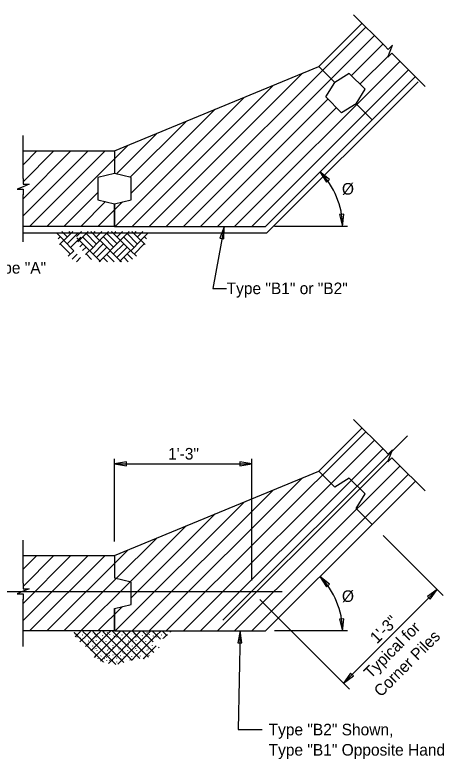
# Model space of a CAD drawing. Extents: x 0.4 to 30.4, y 0.1 to 19.4.
# Drawn here: x 11.03 to 16.63, y 0.42 to 10.14 of the extents above; entities that cross this region are included whole.
import ezdxf

# ---------------------------------------------------------------- set-up
doc = ezdxf.new("R2010")
doc.units = 0
for name, color, linetype in [('Dimension', 7, 'Continuous'), ('Miscellaneous', 7, 'Continuous'), ('SheetPileConc', 7, 'Continuous'), ('TextStructures', 7, 'Continuous')]:
    doc.layers.add(name, color=color, linetype=linetype)

msp = doc.modelspace()

# ---------------------------------------------------------------- linework, layer by layer
at = {"layer": 'Dimension'}
for p, q in [((15.4473, 10.1428), (15.8492, 9.7409)), ((15.9982, 9.5919), (16.3805, 9.2096)), ((14.3167, 7.295), (16.2894, 9.2679)), ((11.1364, 8.0057), (11.1364, 8.5658)), ((11.1364, 7.1795), (11.1364, 7.7951)), ((11.1364, 7.295), (14.3167, 7.295)), ((15.3652, 7.3812), (14.416, 7.3812)), ((15.4473, 4.8586), (15.8492, 4.4567)), ((12.3278, 3.2671), (12.3278, 4.3456)), ((12.3278, 4.2799), (14.1178, 4.2799)), ((14.1178, 2.7541), (14.1178, 4.3456)), ((15.9982, 4.3077), (16.3805, 3.9254)), ((15.8338, 3.3439), (16.6166, 2.5612)), ((11.1364, 2.7215), (11.1364, 3.2816)), ((15.315, 1.4172), (16.5378, 2.64)), ((11.1364, 1.8953), (11.1364, 2.5109)), ((14.2235, 2.5087), (15.3938, 1.3384)), ((15.3652, 2.097), (14.416, 2.097))]:
    msp.add_line(p, q, dxfattribs=at)
for points in [[(15.998, 9.5921), (15.9467, 9.6434), (15.8919, 9.5886), (15.9229, 9.6672), (15.9538, 9.7459), (15.899, 9.6911), (15.8478, 9.7423)], [(11.1364, 8.0055), (11.1364, 7.933), (11.2139, 7.933), (11.1364, 7.8993), (11.0589, 7.8655), (11.1364, 7.8655), (11.1364, 7.793)], [(13.7593, 7.3769), (13.6131, 6.5692), (13.7903, 6.5692)], [(15.998, 4.3079), (15.9467, 4.3592), (15.8919, 4.3044), (15.9229, 4.383), (15.9538, 4.4617), (15.899, 4.4069), (15.8478, 4.4581)], [(11.1364, 2.7213), (11.1364, 2.6488), (11.2139, 2.6488), (11.1364, 2.615), (11.0589, 2.5813), (11.1364, 2.5813), (11.1364, 2.5088)], [(13.9657, 2.097), (13.9426, 0.8111), (14.2532, 0.8111)]]:
    msp.add_lwpolyline(points, dxfattribs=at)
for points in [[(15.0078, 8.0922), (15.0925, 7.9584), (15.1318, 7.9937)], [(15.3028, 7.3805), (15.3176, 7.5382), (15.2648, 7.5342)], [(13.7593, 7.3769), (13.7027, 7.2289), (13.7546, 7.2186)], [(12.3278, 4.2798), (12.484, 4.2534), (12.484, 4.3063)], [(14.1178, 4.2798), (13.9616, 4.3063), (13.9616, 4.2534)], [(15.0078, 2.808), (15.0925, 2.6741), (15.1318, 2.7095)], [(16.5378, 2.64), (16.4086, 2.5483), (16.446, 2.5108)], [(15.3028, 2.0962), (15.3176, 2.254), (15.2648, 2.25)], [(13.9657, 2.097), (13.9356, 1.9415), (13.9885, 1.9403)], [(15.315, 1.4172), (15.4442, 1.509), (15.4067, 1.5464)]]:
    msp.add_lwpolyline(points, close=True, dxfattribs=at)
for centre in [(14.2966, 7.3812), (14.2966, 2.097)]:
    msp.add_arc(centre, 1.0053, 0, 45.00083, dxfattribs=at)
at = {"layer": 'Miscellaneous'}
for p, q in [((13.004, 7.3812), (15.6065, 9.9836)), ((13.2268, 7.3812), (15.7178, 9.8723)), ((15.4182, 9.35), (15.8292, 9.7609)), ((13.8949, 7.3812), (16.0519, 9.5382)), ((15.5296, 9.2386), (15.9007, 9.6097)), ((12.7813, 7.3812), (14.7824, 9.3823)), ((14.1177, 7.3812), (16.1633, 9.4268)), ((12.5586, 7.3812), (14.4021, 9.2248)), ((12.3358, 7.3812), (14.0219, 9.0673)), ((13.4495, 7.3812), (15.112, 9.0437)), ((12.5444, 7.8125), (13.6417, 8.9098)), ((13.6723, 7.3812), (15.2233, 8.9324)), ((12.5313, 8.0222), (13.2615, 8.7524)), ((12.3512, 8.0648), (12.8813, 8.5949)), ((11.1364, 7.7409), (11.7611, 8.3657)), ((11.1364, 7.5182), (11.9838, 8.3657)), ((11.1364, 8.1864), (11.3156, 8.3657)), ((11.1364, 7.9637), (11.5383, 8.3657)), ((11.2221, 7.3812), (12.2065, 8.3657)), ((11.4449, 7.3812), (12.501, 8.4374)), ((11.6676, 7.3812), (12.1113, 7.8249)), ((11.8904, 7.3812), (12.2128, 7.7037)), ((12.1131, 7.3812), (12.4333, 7.7016)), ((11.5768, 7.2907), (11.6664, 7.2011)), ((11.6426, 7.3132), (11.7105, 7.2453)), ((11.7841, 7.3132), (11.6692, 7.1983)), ((11.7311, 7.3132), (11.7548, 7.2895)), ((11.8324, 7.2482), (11.8974, 7.3132)), ((11.9859, 7.3132), (11.8519, 7.1792)), ((12.0204, 7.3132), (12.1353, 7.1983)), ((12.0733, 7.3132), (12.0496, 7.2895)), ((12.1619, 7.3132), (12.0939, 7.2453)), ((12.2501, 7.3132), (12.138, 7.2011)), ((12.5211, 7.3132), (12.2735, 7.0657)), ((12.2904, 7.3132), (12.5379, 7.0658)), ((12.3174, 7.2863), (12.3442, 7.3132)), ((12.3615, 7.2422), (12.4325, 7.3132)), ((12.5555, 7.3132), (12.6704, 7.1983)), ((12.6085, 7.3132), (12.5848, 7.2895)), ((12.697, 7.3132), (12.629, 7.2453)), ((12.7627, 7.2907), (12.6732, 7.2011)), ((11.6193, 7.2426), (11.5939, 7.2172)), ((11.6636, 7.1983), (11.61, 7.1447)), ((11.7989, 7.063), (11.6664, 7.1955)), ((11.8456, 7.2861), (11.7135, 7.1541)), ((11.8897, 7.242), (11.7576, 7.1099)), ((11.8371, 7.2313), (12.0027, 7.0658)), ((11.9148, 7.242), (12.0468, 7.1099)), ((11.9589, 7.2861), (12.091, 7.1541)), ((12.0055, 7.063), (12.138, 7.1955)), ((12.1408, 7.1983), (12.2735, 7.0657)), ((12.1851, 7.2426), (12.3178, 7.1099)), ((12.2292, 7.2867), (12.3619, 7.1541)), ((12.4499, 7.242), (12.582, 7.1099)), ((12.494, 7.2861), (12.6261, 7.1541)), ((12.5406, 7.063), (12.6732, 7.1955)), ((12.676, 7.1983), (12.7296, 7.1447)), ((12.7202, 7.2426), (12.7456, 7.2172)), ((11.7546, 7.0187), (11.6221, 7.1512)), ((11.9143, 7.1542), (11.8755, 7.1153)), ((11.9586, 7.1099), (11.9136, 7.0649)), ((12.0498, 7.0187), (12.1823, 7.1512)), ((12.0939, 6.9746), (12.2264, 7.1071)), ((12.4494, 7.1542), (12.3172, 7.0219)), ((12.4937, 7.1099), (12.3615, 6.9776)), ((12.5849, 7.0187), (12.7174, 7.1512)), ((11.7989, 7.063), (11.7255, 6.9896)), ((11.8428, 7.0192), (11.7775, 6.9538)), ((12.0027, 7.0658), (11.9517, 7.0147)), ((11.9617, 7.0192), (12.0308, 6.95)), ((12.0055, 7.063), (12.1473, 6.9213)), ((12.2707, 7.0629), (12.1273, 6.9195)), ((12.2264, 7.0186), (12.3256, 6.9195)), ((12.2707, 7.0629), (12.4028, 6.9307)), ((12.5379, 7.0658), (12.4056, 6.9335)), ((12.4968, 7.0192), (12.5621, 6.9538)), ((12.5406, 7.063), (12.614, 6.9896)), ((11.8869, 6.975), (11.8313, 6.9195)), ((12.1823, 6.9745), (12.2373, 6.9195)), ((12.3971, 6.9195), (12.4056, 6.928)), ((12.4084, 6.9307), (12.4197, 6.9195)), ((12.4527, 6.975), (12.5082, 6.9195)), ((13.004, 2.097), (15.6065, 4.6994)), ((13.2268, 2.097), (15.7178, 4.5881)), ((16.1502, 4.6468), (13.7399, 2.2366)), ((15.4182, 4.0658), (15.8292, 4.4767)), ((15.5296, 3.9544), (15.9007, 4.3255)), ((13.4495, 2.097), (15.5346, 4.1822)), ((13.8949, 2.097), (16.0519, 4.254)), ((12.7813, 2.097), (14.7824, 4.0981)), ((14.1177, 2.097), (16.1633, 4.1426)), ((12.5586, 2.097), (14.4021, 3.9406)), ((13.6723, 2.097), (15.5296, 3.9544)), ((12.3358, 2.097), (14.0219, 3.7831)), ((12.5444, 2.5283), (13.6417, 3.6256)), ((12.5313, 2.738), (13.2615, 3.4682)), ((12.3512, 2.7806), (12.8813, 3.3107)), ((11.4449, 2.097), (12.501, 3.1532)), ((11.1364, 2.4567), (11.7611, 3.0814)), ((11.1364, 2.234), (11.9838, 3.0814)), ((11.1364, 2.9022), (11.3156, 3.0814)), ((11.1364, 2.6795), (11.5383, 3.0814)), ((11.2221, 2.097), (12.2065, 3.0814)), ((11.6676, 2.097), (12.3512, 2.7806)), ((11.8904, 2.097), (12.5444, 2.7511)), ((10.7426, 2.6144), (11.1364, 2.6144)), ((11.1364, 2.6144), (14.5141, 2.6144)), ((12.1131, 2.097), (12.4333, 2.4173)), ((11.805, 2.0789), (11.8055, 2.0814)), ((11.8356, 2.0407), (11.8072, 2.0691)), ((11.8356, 2.0407), (11.8858, 2.091)), ((11.8769, 2.0709), (11.8754, 2.0717)), ((11.9115, 2.0438), (11.9085, 2.0424)), ((11.9658, 2.0407), (11.9155, 2.0911)), ((11.943, 2.0626), (11.9423, 2.0641)), ((11.9658, 2.0407), (12.0164, 2.0914)), ((11.9799, 2.0461), (11.9806, 2.0491)), ((12.0373, 2.0621), (12.0381, 2.0651)), ((12.0957, 2.041), (12.0452, 2.0915)), ((12.0735, 2.0543), (12.0742, 2.0574)), ((12.096, 2.0407), (12.1471, 2.0918)), ((12.2262, 2.0407), (12.175, 2.0919)), ((12.1945, 2.0867), (12.19, 2.0859)), ((12.2262, 2.0407), (12.2777, 2.0923)), ((12.2359, 2.0739), (12.2351, 2.0754)), ((12.2667, 2.0506), (12.2674, 2.0536)), ((12.3564, 2.0407), (12.3048, 2.0924)), ((12.3216, 2.0777), (12.3224, 2.0814)), ((12.3564, 2.0407), (12.4084, 2.0927)), ((12.3938, 2.0709), (12.3923, 2.0717)), ((12.4284, 2.0438), (12.4254, 2.0424)), ((12.4866, 2.0407), (12.4345, 2.0928)), ((12.4599, 2.0626), (12.4592, 2.0641)), ((12.4866, 2.0407), (12.539, 2.0932)), ((12.4968, 2.0461), (12.4975, 2.0491)), ((12.5542, 2.0621), (12.555, 2.0651)), ((12.6166, 2.041), (12.5643, 2.0933)), ((12.5904, 2.0543), (12.5911, 2.0574)), ((12.6168, 2.0407), (12.6697, 2.0936)), ((12.747, 2.0407), (12.6941, 2.0937)), ((12.7114, 2.0867), (12.7069, 2.0859)), ((12.747, 2.0407), (12.8003, 2.0941)), ((12.7527, 2.0739), (12.752, 2.0754)), ((12.7836, 2.0506), (12.7843, 2.0536)), ((12.8772, 2.0407), (12.8239, 2.0941)), ((12.8385, 2.0777), (12.8393, 2.0814)), ((12.8772, 2.0407), (12.931, 2.0945)), ((12.9107, 2.0709), (12.9092, 2.0717)), ((12.9453, 2.0438), (12.9423, 2.0424)), ((13.0074, 2.0407), (12.9536, 2.0946)), ((12.9768, 2.0626), (12.9761, 2.0641)), ((13.0074, 2.0407), (13.0189, 2.0522)), ((13.0137, 2.0461), (13.0144, 2.0491)), ((13.0512, 2.0845), (13.0616, 2.0949)), ((11.8179, 2.0231), (11.8356, 2.0407)), ((12.096, 1.7803), (11.8356, 2.0407)), ((11.8423, 2.0152), (11.843, 2.0183)), ((11.8785, 1.9534), (11.9658, 2.0407)), ((11.8897, 1.998), (11.8859, 1.9973)), ((11.9318, 1.9995), (11.9303, 2.0017)), ((11.9499, 1.8947), (12.096, 2.0407)), ((11.9505, 1.9927), (11.9521, 1.9957)), ((11.9505, 1.9453), (11.9521, 1.9484)), ((12.096, 1.9105), (11.9658, 2.0407)), ((11.994, 1.9634), (11.9902, 1.9626)), ((12.0532, 1.9634), (12.0494, 1.9626)), ((12.0666, 2.0017), (12.0674, 2.0047)), ((12.0923, 2.0168), (12.093, 2.0198)), ((12.0923, 1.9686), (12.093, 1.9717)), ((12.4504, 1.6863), (12.096, 2.0407)), ((12.096, 1.7803), (12.3564, 2.0407)), ((12.096, 1.9105), (12.2262, 2.0407)), ((12.1467, 1.7008), (12.4866, 2.0407)), ((12.1742, 2.0355), (12.1757, 2.0386)), ((12.1742, 1.9882), (12.1757, 1.9912)), ((12.1795, 1.9611), (12.1765, 1.9604)), ((12.2186, 2.0017), (12.2186, 2.0047)), ((12.2186, 1.9543), (12.2186, 1.9573)), ((12.5531, 1.7138), (12.2262, 2.0407)), ((12.2359, 2.0265), (12.2351, 2.028)), ((12.2502, 1.6741), (12.6168, 2.0407)), ((12.2772, 1.9596), (12.2735, 1.9588)), ((12.3216, 2.0303), (12.3224, 2.034)), ((12.6168, 1.7803), (12.3564, 2.0407)), ((12.3592, 2.0152), (12.3599, 2.0183)), ((12.3855, 1.9499), (12.387, 1.9528)), ((12.387, 1.9484), (12.3877, 1.9514)), ((12.4066, 1.998), (12.4028, 1.9973)), ((12.4487, 1.9995), (12.4472, 2.0017)), ((12.4674, 1.9927), (12.469, 1.9957)), ((12.4674, 1.9453), (12.469, 1.9484)), ((12.6168, 1.9105), (12.4866, 2.0407)), ((12.5109, 1.9634), (12.5071, 1.9626)), ((12.5701, 1.9634), (12.5663, 1.9626)), ((12.5835, 2.0017), (12.5843, 2.0047)), ((12.6092, 2.0168), (12.6099, 2.0198)), ((12.6092, 1.9686), (12.6099, 1.9717)), ((12.8415, 1.816), (12.6168, 2.0407)), ((12.6168, 1.7803), (12.8772, 2.0407)), ((12.6168, 1.9105), (12.747, 2.0407)), ((12.6911, 2.0355), (12.6926, 2.0386)), ((12.6911, 1.9882), (12.6926, 1.9912)), ((12.6964, 1.9611), (12.6934, 1.9604)), ((12.7355, 2.0017), (12.7355, 2.0047)), ((12.7355, 1.9543), (12.7355, 1.9573)), ((12.8333, 1.9544), (12.747, 2.0407)), ((12.7527, 2.0265), (12.752, 2.028)), ((12.7941, 1.9596), (12.7904, 1.9588)), ((12.8385, 2.0303), (12.8393, 2.034)), ((12.8761, 2.0152), (12.8768, 2.0183)), ((12.9297, 1.9883), (12.8772, 2.0407)), ((12.9234, 1.998), (12.9197, 1.9973)), ((12.9648, 2.0006), (12.9641, 2.0017)), ((12.9687, 2.002), (13.0074, 2.0407)), ((13.0118, 2.0363), (13.0074, 2.0407)), ((11.994, 1.916), (11.9902, 1.9152)), ((12.0213, 1.8359), (12.096, 1.9105)), ((12.0475, 1.9002), (12.0483, 1.9032)), ((12.0652, 1.8739), (12.0614, 1.8732)), ((12.072, 1.8513), (12.0715, 1.8522)), ((12.0907, 1.8648), (12.0915, 1.8679)), ((12.3478, 1.6587), (12.096, 1.9105)), ((12.1021, 1.843), (12.1036, 1.8468)), ((12.1178, 1.931), (12.1133, 1.931)), ((12.1351, 1.8717), (12.1359, 1.8746)), ((12.1517, 1.9017), (12.1502, 1.9025)), ((12.2268, 1.9032), (12.2276, 1.9062)), ((12.2562, 1.9077), (12.2554, 1.9092)), ((12.2562, 1.8604), (12.2554, 1.8619)), ((12.3088, 1.9032), (12.3096, 1.9062)), ((12.3088, 1.8792), (12.3096, 1.8821)), ((12.3366, 1.9318), (12.3389, 1.9348)), ((12.3366, 1.8844), (12.3389, 1.8874)), ((12.3714, 1.6651), (12.6168, 1.9105)), ((12.3833, 1.8453), (12.3847, 1.8484)), ((12.387, 1.8611), (12.3877, 1.8641)), ((12.4156, 1.8551), (12.4171, 1.8588)), ((12.4284, 1.9198), (12.4269, 1.9221)), ((12.4667, 1.8874), (12.466, 1.8889)), ((12.4698, 1.8897), (12.4667, 1.8897)), ((12.5109, 1.916), (12.5071, 1.9152)), ((12.5644, 1.9002), (12.5652, 1.9032)), ((12.5821, 1.8739), (12.5783, 1.8732)), ((12.5889, 1.8513), (12.5884, 1.8522)), ((12.6076, 1.8648), (12.6084, 1.8679)), ((12.7737, 1.7536), (12.6168, 1.9105)), ((12.619, 1.843), (12.6205, 1.8468)), ((12.6347, 1.931), (12.6302, 1.931)), ((12.652, 1.8717), (12.6527, 1.8746)), ((12.6686, 1.9017), (12.6671, 1.9025)), ((12.7016, 1.7349), (12.8705, 1.9038)), ((12.7437, 1.9032), (12.7445, 1.9062)), ((12.7731, 1.9077), (12.7723, 1.9092)), ((12.7731, 1.8604), (12.7723, 1.8619)), ((12.8257, 1.9032), (12.8264, 1.9062)), ((12.8257, 1.8792), (12.8264, 1.8821)), ((12.8535, 1.8844), (12.8558, 1.8874)), ((12.9093, 1.8785), (12.9009, 1.8868)), ((12.046, 1.8273), (12.0467, 1.8303)), ((12.0668, 1.7511), (12.096, 1.7803)), ((12.072, 1.804), (12.0712, 1.8055)), ((12.1855, 1.6908), (12.096, 1.7803)), ((12.152, 1.7675), (12.1528, 1.7704)), ((12.1525, 1.8401), (12.154, 1.843)), ((12.1765, 1.8273), (12.1728, 1.8265)), ((12.2224, 1.7957), (12.2201, 1.798)), ((12.2224, 1.7484), (12.2201, 1.7506)), ((12.2359, 1.843), (12.2321, 1.8415)), ((12.2622, 1.8085), (12.263, 1.8115)), ((12.263, 1.7716), (12.2637, 1.7747)), ((12.3118, 1.8288), (12.3134, 1.8325)), ((12.3118, 1.7814), (12.3134, 1.7852)), ((12.3389, 1.7897), (12.3396, 1.7927)), ((12.4111, 1.7723), (12.4073, 1.7716)), ((12.4351, 1.8227), (12.4359, 1.8258)), ((12.4532, 1.801), (12.451, 1.8017)), ((12.4532, 1.7536), (12.451, 1.7544)), ((12.5006, 1.8378), (12.5021, 1.8408)), ((12.5006, 1.7904), (12.5021, 1.7934)), ((12.53, 1.7887), (12.5308, 1.7918)), ((12.5493, 1.7128), (12.6168, 1.7803)), ((12.5539, 1.7605), (12.5546, 1.7635)), ((12.5629, 1.8273), (12.5636, 1.8303)), ((12.5889, 1.804), (12.5881, 1.8055)), ((12.6586, 1.7385), (12.6168, 1.7803)), ((12.6689, 1.7675), (12.6697, 1.7704)), ((12.6693, 1.8401), (12.6708, 1.843)), ((12.6934, 1.8273), (12.6897, 1.8265)), ((12.7393, 1.7957), (12.737, 1.798)), ((12.7393, 1.7484), (12.737, 1.7506)), ((12.7527, 1.843), (12.749, 1.8415)), ((12.7791, 1.8085), (12.7799, 1.8115)), ((12.7799, 1.7716), (12.7806, 1.7747)), ((12.8287, 1.8288), (12.8303, 1.8325)), ((12.1163, 1.7325), (12.117, 1.7356)), ((12.1998, 1.7356), (12.196, 1.7348)), ((12.1998, 1.6882), (12.1974, 1.6877)), ((12.2268, 1.7062), (12.2276, 1.7093)), ((12.2667, 1.7062), (12.2674, 1.7093)), ((12.302, 1.7111), (12.3028, 1.7141)), ((12.3577, 1.7363), (12.3592, 1.7393)), ((12.3577, 1.6889), (12.3592, 1.6919)), ((12.3592, 1.7415), (12.3599, 1.7446)), ((12.4141, 1.704), (12.4111, 1.7032)), ((12.4122, 1.7346), (12.4129, 1.7375)), ((12.4366, 1.7055), (12.4373, 1.7085)), ((12.4855, 1.719), (12.4863, 1.722)), ((12.5317, 1.7169), (12.5332, 1.7199)), ((12.6339, 1.7355), (12.6339, 1.7356)), ((12.7167, 1.7356), (12.7129, 1.7348))]:
    msp.add_line(p, q, dxfattribs=at)
at = {"layer": 'SheetPileConc'}
for p, q in [((14.9926, 9.4694), (15.5566, 10.0335)), ((12.3278, 8.3657), (14.9926, 9.4694)), ((14.9926, 9.4694), (15.2014, 9.2606)), ((15.2014, 9.2606), (14.9926, 9.4694)), ((14.9926, 9.4694), (15.2014, 9.2607)), ((15.3907, 9.3775), (15.2014, 9.2607)), ((15.5967, 9.1716), (15.3907, 9.3775)), ((16.2527, 9.3374), (15.6886, 8.7734)), ((15.0844, 9.0712), (15.2014, 9.2606)), ((15.4798, 8.9822), (15.5967, 9.1716)), ((15.2905, 8.8653), (15.0844, 9.0712)), ((15.4798, 8.9822), (15.2905, 8.8653)), ((15.4798, 8.9822), (15.6886, 8.7734)), ((15.6886, 8.7734), (15.4798, 8.9822)), ((15.6886, 8.7734), (15.4798, 8.9822)), ((14.2965, 7.3812), (15.6886, 8.7734)), ((11.1364, 8.3657), (12.3278, 8.3657)), ((12.3278, 8.3657), (12.3278, 8.0704)), ((12.3278, 8.3657), (12.3278, 8.0703)), ((12.3278, 8.0703), (12.1113, 8.0192)), ((12.5444, 8.0192), (12.3278, 8.0704)), ((12.1113, 8.0192), (12.1113, 7.7278)), ((12.5444, 7.7278), (12.5444, 8.0192)), ((12.1113, 7.7278), (12.3278, 7.6766)), ((12.3278, 7.6766), (12.5444, 7.7278)), ((12.3278, 7.6766), (12.3278, 7.3812)), ((12.3278, 7.3812), (12.3278, 7.6766)), ((12.3278, 7.3812), (11.1364, 7.3812)), ((12.3278, 7.3812), (14.2965, 7.3812)), ((14.9926, 4.1852), (15.5566, 4.7493)), ((12.3278, 3.0814), (14.9926, 4.1852)), ((14.9926, 4.1852), (15.2014, 3.9764)), ((15.2014, 3.9764), (14.9926, 4.1852)), ((14.9926, 4.1852), (15.2014, 3.9764)), ((15.3907, 4.0933), (15.2014, 3.9764)), ((15.5967, 3.8873), (15.3907, 4.0933)), ((16.2527, 4.0532), (15.6886, 3.4892)), ((15.4798, 3.698), (15.5967, 3.8873)), ((15.4798, 3.698), (15.6886, 3.4892)), ((15.6886, 3.4892), (15.4798, 3.698)), ((15.6886, 3.4892), (15.4798, 3.698)), ((14.2965, 2.097), (15.6886, 3.4892)), ((11.1364, 3.0814), (12.3278, 3.0814)), ((12.3278, 3.0814), (12.3278, 2.7861)), ((12.3278, 3.0814), (12.3278, 2.7861)), ((12.5444, 2.7349), (12.3278, 2.7861)), ((12.5444, 2.4436), (12.5444, 2.7349)), ((12.3278, 2.3924), (12.5444, 2.4436)), ((12.3278, 2.3924), (12.3278, 2.097)), ((12.3278, 2.097), (12.3278, 2.3923)), ((12.3278, 2.097), (11.1364, 2.097)), ((12.3278, 2.097), (14.2965, 2.097))]:
    msp.add_line(p, q, dxfattribs=at)

# ---------------------------------------------------------------- texts
at = {"layer": 'Dimension'}
for s, p in [('1\'-3"', (15.7515, 1.922)), ('Typical for', (15.67, 1.4671)), ('Corner Piles', (15.8025, 1.2262))]:
    msp.add_text(s, height=0.1512, rotation=45, dxfattribs=at).set_placement(p)
at = {"layer": 'TextStructures'}
for s, p in [('Ø', (15.2945, 7.7958)), ('Type "A"', (10.653, 6.7643)), ('Type "B1" or "B2"', (13.7909, 6.496)), ('1\'-3"', (13.0272, 4.3358)), ('Ø', (15.2945, 2.4761)), ('Type "B2" Shown,', (14.3383, 0.7336)), ('Type "B1" Opposite Hand', (14.3383, 0.469))]:
    msp.add_text(s, height=0.1512, dxfattribs=at).set_placement(p)

doc.saveas('drawing.dxf')
